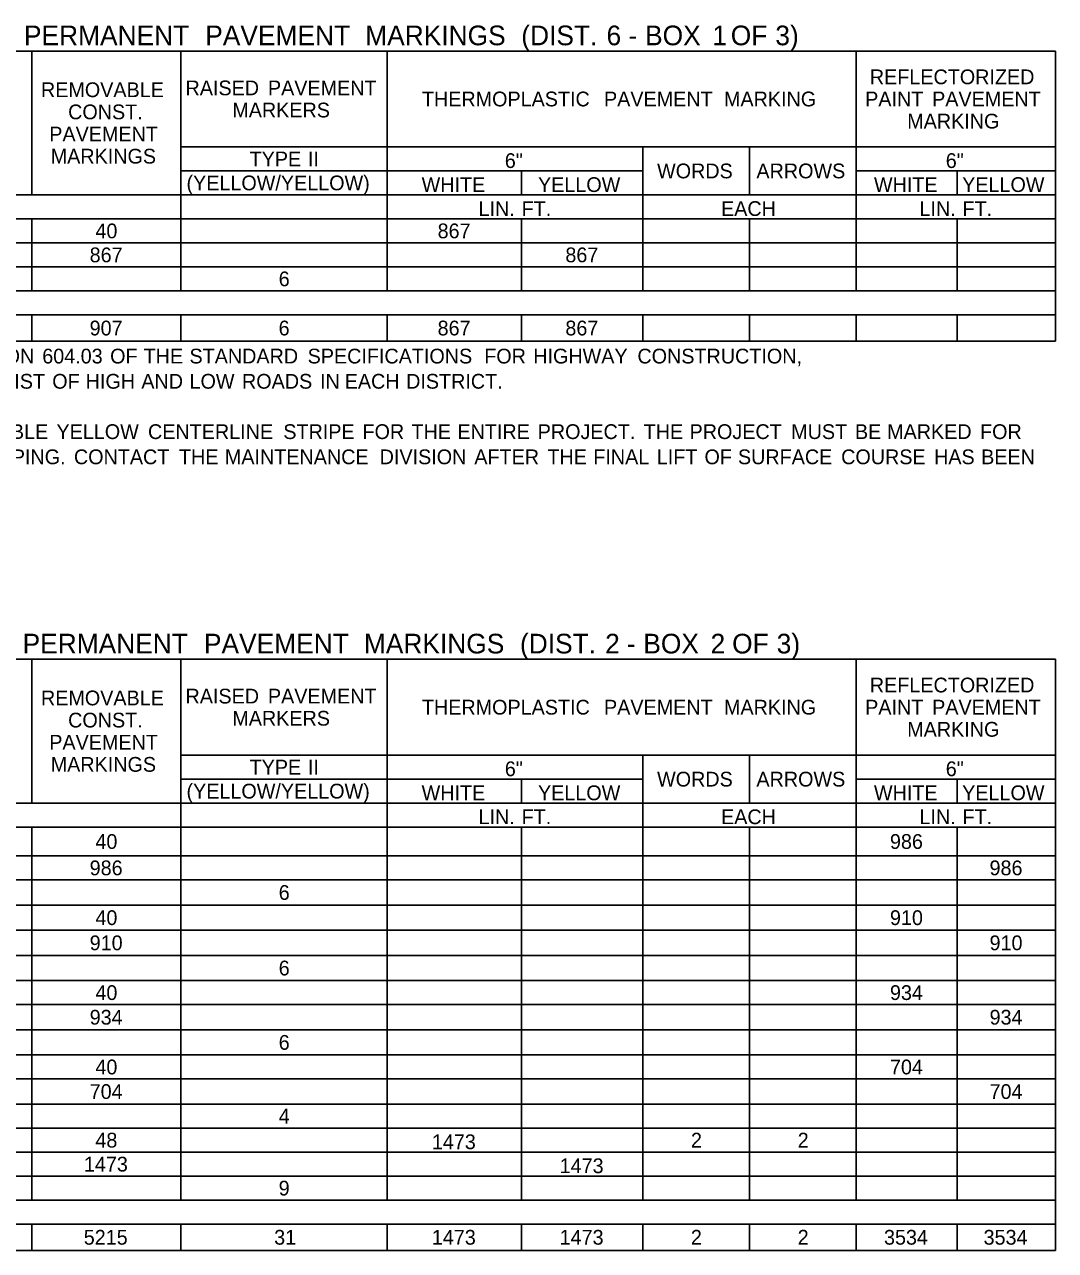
# Model space of a CAD drawing. Extents: x 542596 to 1930787, y -1948294 to 596640.
# Drawn here: x 558149.1 to 558568, y -1946597.7 to -1946099.4 of the extents above; entities that cross this region are included whole.
import ezdxf

# ---------------------------------------------------------------- set-up
doc = ezdxf.new("R2010")
doc.units = 0
doc.layers.add('Default', color=7, linetype='Continuous')

msp = doc.modelspace()

# ---------------------------------------------------------------- linework, layer by layer
at = {"layer": 'Default'}
for p, q in [((557797.21, -1946110.14), (558567.95, -1946110.14)), ((558152.11, -1946168.64), (558152.11, -1946110.14)), ((558212.56, -1946207.64), (558212.56, -1946110.14)), ((558296.41, -1946207.64), (558296.41, -1946110.14)), ((558487.03, -1946207.64), (558487.03, -1946110.14)), ((558567.95, -1946228.11), (558567.95, -1946110.14)), ((558212.56, -1946149.14), (558567.95, -1946149.14)), ((558400.25, -1946207.64), (558400.25, -1946149.14)), ((558400.25, -1946207.64), (558400.25, -1946149.14)), ((558443.64, -1946168.64), (558443.64, -1946149.14)), ((558212.56, -1946158.89), (558400.25, -1946158.89)), ((558351.01, -1946168.64), (558351.01, -1946158.89)), ((558487.03, -1946158.89), (558567.95, -1946158.89)), ((558527.98, -1946168.64), (558527.98, -1946158.89)), ((558031.21, -1946168.64), (558567.95, -1946168.64)), ((558212.56, -1946207.64), (558212.56, -1946168.64)), ((558400.25, -1946168.64), (558567.95, -1946168.64)), ((557797.21, -1946178.39), (558567.95, -1946178.39)), ((558152.11, -1946207.64), (558152.11, -1946178.39)), ((558152.11, -1946207.64), (558152.11, -1946178.39)), ((558296.41, -1946207.64), (558296.41, -1946178.39)), ((558351.01, -1946197.89), (558351.01, -1946178.39)), ((558351.01, -1946207.64), (558351.01, -1946178.39)), ((558443.64, -1946207.64), (558443.64, -1946178.39)), ((558443.64, -1946207.64), (558443.64, -1946178.39)), ((558487.03, -1946207.64), (558487.03, -1946178.39)), ((558527.98, -1946197.89), (558527.98, -1946178.39)), ((558527.98, -1946207.64), (558527.98, -1946178.39)), ((557971.25, -1946188.14), (558567.95, -1946188.14)), ((557971.25, -1946197.89), (558567.95, -1946197.89)), ((557797.21, -1946207.64), (558296.41, -1946207.64)), ((558091.66, -1946207.64), (558212.56, -1946207.64)), ((558212.56, -1946207.64), (558567.95, -1946207.64)), ((557797.21, -1946217.39), (558567.95, -1946217.39)), ((557797.21, -1946217.39), (558567.95, -1946217.39)), ((558152.11, -1946228.11), (558152.11, -1946217.39)), ((558152.11, -1946228.11), (558152.11, -1946217.39)), ((558212.56, -1946228.11), (558212.56, -1946217.39)), ((558212.56, -1946228.11), (558212.56, -1946217.39)), ((558296.41, -1946228.11), (558296.41, -1946217.39)), ((558296.41, -1946228.11), (558296.41, -1946217.39)), ((558351.01, -1946228.11), (558351.01, -1946217.39)), ((558351.01, -1946228.11), (558351.01, -1946217.39)), ((558400.25, -1946228.11), (558400.25, -1946217.39)), ((558400.25, -1946228.11), (558400.25, -1946217.39)), ((558443.64, -1946228.11), (558443.64, -1946217.39)), ((558443.64, -1946228.11), (558443.64, -1946217.39)), ((558487.03, -1946228.11), (558487.03, -1946217.39)), ((558487.03, -1946228.11), (558487.03, -1946217.39)), ((558527.98, -1946228.11), (558527.98, -1946217.39)), ((558527.98, -1946228.11), (558527.98, -1946217.39)), ((557797.21, -1946228.11), (558567.95, -1946228.11)), ((557797.21, -1946357.36), (558567.95, -1946357.36)), ((558152.11, -1946415.86), (558152.11, -1946357.36)), ((558212.56, -1946577.22), (558212.56, -1946357.36)), ((558296.41, -1946577.22), (558296.41, -1946357.36)), ((558487.03, -1946577.22), (558487.03, -1946357.36)), ((558567.95, -1946497.76), (558567.95, -1946357.36)), ((558212.56, -1946396.36), (558567.95, -1946396.36)), ((558400.25, -1946577.22), (558400.25, -1946396.36)), ((558400.25, -1946577.22), (558400.25, -1946396.36)), ((558443.64, -1946415.86), (558443.64, -1946396.36)), ((558212.56, -1946406.11), (558400.25, -1946406.11)), ((558351.01, -1946415.86), (558351.01, -1946406.11)), ((558487.03, -1946406.11), (558567.95, -1946406.11)), ((558527.98, -1946415.86), (558527.98, -1946406.11)), ((558031.21, -1946415.86), (558567.95, -1946415.86)), ((558212.56, -1946577.22), (558212.56, -1946415.86)), ((558400.25, -1946415.86), (558567.95, -1946415.86)), ((557797.21, -1946425.61), (558567.95, -1946425.61)), ((558152.11, -1946577.22), (558152.11, -1946425.61)), ((558152.11, -1946577.22), (558152.11, -1946425.61)), ((558212.56, -1946425.61), (558296.41, -1946425.61)), ((558296.41, -1946577.22), (558296.41, -1946425.61)), ((558351.01, -1946425.61), (558567.95, -1946425.61)), ((558351.01, -1946577.22), (558351.01, -1946425.61)), ((558351.01, -1946577.22), (558351.01, -1946425.61)), ((558443.64, -1946577.22), (558443.64, -1946425.61)), ((558443.64, -1946577.22), (558443.64, -1946425.61)), ((558487.03, -1946577.22), (558487.03, -1946425.61)), ((558527.98, -1946577.22), (558527.98, -1946425.61)), ((558527.98, -1946577.22), (558527.98, -1946425.61)), ((557971.25, -1946437.31), (558567.95, -1946437.31)), ((557971.25, -1946447.06), (558567.95, -1946447.06)), ((557797.21, -1946457.3), (558567.95, -1946457.3)), ((557971.25, -1946457.3), (558567.95, -1946457.3)), ((557971.25, -1946467.53), (558567.95, -1946467.53)), ((557971.25, -1946477.77), (558567.95, -1946477.77)), ((557797.21, -1946488.01), (558351.01, -1946488.01)), ((557971.25, -1946488.01), (558296.41, -1946488.01)), ((558296.41, -1946488.01), (558351.01, -1946488.01)), ((558351.01, -1946488.01), (558567.95, -1946488.01)), ((558351.01, -1946488.01), (558567.95, -1946488.01)), ((557971.25, -1946497.76), (558567.95, -1946497.76)), ((558567.95, -1946508), (558567.95, -1946497.76)), ((557971.25, -1946508), (558567.95, -1946508)), ((558351.01, -1946508), (558400.25, -1946508)), ((558400.25, -1946508), (558567.95, -1946508)), ((558567.95, -1946557.72), (558567.95, -1946508)), ((557797.21, -1946518.23), (558567.95, -1946518.23)), ((557971.25, -1946518.23), (558567.95, -1946518.23)), ((557971.25, -1946527.98), (558567.95, -1946527.98)), ((557971.25, -1946538.22), (558567.95, -1946538.22)), ((557797.21, -1946547.97), (558567.95, -1946547.97)), ((557971.25, -1946547.97), (558296.41, -1946547.97)), ((558351.01, -1946547.97), (558567.95, -1946547.97)), ((557971.25, -1946557.72), (558567.95, -1946557.72)), ((558567.95, -1946567.47), (558567.95, -1946557.72)), ((557971.25, -1946567.47), (558567.95, -1946567.47)), ((558351.01, -1946567.47), (558400.25, -1946567.47)), ((558400.25, -1946567.47), (558567.95, -1946567.47)), ((558567.95, -1946586.97), (558567.95, -1946567.47)), ((557797.21, -1946577.22), (558567.95, -1946577.22)), ((557797.21, -1946586.97), (558567.95, -1946586.97)), ((557797.21, -1946586.97), (558567.95, -1946586.97)), ((558152.11, -1946597.7), (558152.11, -1946586.97)), ((558152.11, -1946597.7), (558152.11, -1946586.97)), ((558212.56, -1946597.7), (558212.56, -1946586.97)), ((558212.56, -1946597.7), (558212.56, -1946586.97)), ((558296.41, -1946597.7), (558296.41, -1946586.97)), ((558296.41, -1946597.7), (558296.41, -1946586.97)), ((558351.01, -1946597.7), (558351.01, -1946586.97)), ((558351.01, -1946597.7), (558351.01, -1946586.97)), ((558400.25, -1946597.7), (558400.25, -1946586.97)), ((558400.25, -1946597.7), (558400.25, -1946586.97)), ((558443.64, -1946597.7), (558443.64, -1946586.97)), ((558443.64, -1946597.7), (558443.64, -1946586.97)), ((558487.03, -1946597.7), (558487.03, -1946586.97)), ((558487.03, -1946597.7), (558487.03, -1946586.97)), ((558527.98, -1946597.7), (558527.98, -1946586.97)), ((558527.98, -1946597.7), (558527.98, -1946586.97)), ((558567.95, -1946597.7), (558567.95, -1946586.97)), ((557797.21, -1946597.7), (558567.95, -1946597.7))]:
    msp.add_line(p, q, dxfattribs=at)

# ---------------------------------------------------------------- texts
for s, height, p in [(' PERMANENT', 8, (558145.87, -1946107.8)), (' PAVEMENT', 8, (558219.54, -1946107.8)), (' MARKINGS', 8, (558284.53, -1946107.8)), (' (DIST.', 8, (558347.94, -1946107.8)), (' 6', 8, (558382.57, -1946107.8)), (' BOX', 8, (558398.23, -1946107.8)), (' 1', 8, (558425.55, -1946107.8)), (' OF', 8, (558433.05, -1946107.8)), (' 3)', 8, (558451.16, -1946107.8)), (' -', 8, (558391.49, -1946107.8)), ('REFLECTORIZED', 6, (558492.53, -1946123.64)), ('REMOVABLE', 6, (558155.76, -1946128.89)), ('RAISED', 6, (558214.49, -1946128.14)), (' PAVEMENT', 6, (558245.75, -1946128.14)), ('THERMOPLASTIC', 6, (558310.53, -1946132.64)), (' PAVEMENT', 6, (558382.3, -1946132.64)), (' MARKING', 6, (558431.04, -1946132.64)), ('PAINT', 6, (558490.63, -1946132.64)), (' PAVEMENT', 6, (558515.61, -1946132.64)), ('CONST.', 6, (558166.79, -1946137.89)), ('MARKERS', 6, (558233.5, -1946137.14)), ('MARKING', 6, (558507.72, -1946141.64)), ('PAVEMENT', 6, (558159.13, -1946146.89)), ('MARKINGS', 6, (558159.72, -1946155.89)), ('TYPE', 6, (558240.53, -1946157.01)), (' II', 6, (558262.01, -1946157.01)), ('6"', 6, (558344.22, -1946157.69)), ('6"', 6, (558523.38, -1946157.69)), ('WORDS', 6, (558406.08, -1946161.89)), ('ARROWS', 6, (558446.44, -1946161.89)), ('(YELLOW/YELLOW)', 6, (558214.89, -1946166.76)), ('WHITE', 6, (558310.42, -1946167.44)), ('YELLOW', 6, (558357.71, -1946167.44)), ('WHITE', 6, (558494.2, -1946167.44)), ('YELLOW', 6, (558530.04, -1946167.44)), ('LIN.', 6, (558333.54, -1946177.19)), (' FT.', 6, (558348.8, -1946177.19)), ('EACH', 6, (558432.08, -1946177.19)), ('LIN.', 6, (558512.7, -1946177.19)), (' FT.', 6, (558527.95, -1946177.19)), ('40', 6, (558177.88, -1946186.26)), ('867', 6, (558316.91, -1946186.26)), ('867', 6, (558175.54, -1946196.01)), ('867', 6, (558368.83, -1946196.01)), ('6', 6, (558252.35, -1946205.76)), ('907', 6, (558175.53, -1946225.75)), ('6', 6, (558252.31, -1946225.75)), ('867', 6, (558316.91, -1946225.75)), ('867', 6, (558368.83, -1946225.75)), (' SECTION', 6, (558115.15, -1946237.15)), (' 604.03', 6, (558154.05, -1946237.15)), (' OF', 6, (558181.63, -1946237.15)), (' THE', 6, (558195.22, -1946237.15)), (' STANDARD', 6, (558213.87, -1946237.15)), (' SPECIFICATIONS', 6, (558261.87, -1946237.15)), (' FOR', 6, (558333.63, -1946237.15)), (' HIGHWAY', 6, (558353.55, -1946237.15)), (' CONSTRUCTION,', 6, (558395.87, -1946237.15)), (' LIST', 6, (558138.24, -1946247.39)), (' OF', 6, (558158.11, -1946247.39)), (' HIGH', 6, (558171.69, -1946247.39)), (' AND', 6, (558194.3, -1946247.39)), (' LOW', 6, (558213.89, -1946247.39)), (' ROADS', 6, (558235.21, -1946247.39)), (' IN', 6, (558266.92, -1946247.39)), (' EACH', 6, (558276.94, -1946247.39)), (' DISTRICT.', 6, (558301.89, -1946247.39)), (' DOUBLE', 6, (558123.49, -1946267.86)), (' YELLOW', 6, (558159.84, -1946267.86)), (' CENTERLINE', 6, (558197.01, -1946267.86)), (' STRIPE', 6, (558252, -1946267.86)), (' FOR', 6, (558284.17, -1946267.86)), (' THE', 6, (558304.08, -1946267.86)), (' ENTIRE', 6, (558322.73, -1946267.86)), (' PROJECT.', 6, (558355.35, -1946267.86)), (' THE', 6, (558398.41, -1946267.86)), (' PROJECT', 6, (558417.06, -1946267.86)), (' MUST', 6, (558458.35, -1946267.86)), (' BE', 6, (558484.26, -1946267.86)), (' MARKED', 6, (558497.33, -1946267.86)), (' FOR', 6, (558535.08, -1946267.86)), (' STRIPING.', 6, (558123.4, -1946278.1)), (' CONTACT', 6, (558166.92, -1946278.1)), (' THE', 6, (558209.6, -1946278.1)), (' MAINTENANCE', 6, (558228.25, -1946278.1)), (' DIVISION', 6, (558291.15, -1946278.1)), (' AFTER', 6, (558329.6, -1946278.1)), (' THE', 6, (558359.29, -1946278.1)), (' FINAL', 6, (558377.94, -1946278.1)), (' LIFT', 6, (558403.73, -1946278.1)), (' OF', 6, (558423.12, -1946278.1)), (' SURFACE', 6, (558436.71, -1946278.1)), (' COURSE', 6, (558478.65, -1946278.1)), (' HAS', 6, (558516.4, -1946278.1)), (' BEEN', 6, (558535.53, -1946278.1)), (' PERMANENT', 8, (558145.32, -1946355.02)), (' PAVEMENT', 8, (558219, -1946355.02)), (' MARKINGS', 8, (558283.99, -1946355.02)), (' (DIST.', 8, (558347.4, -1946355.02)), (' 2', 8, (558382.02, -1946355.02)), (' BOX', 8, (558397.52, -1946355.02)), (' 2', 8, (558424.84, -1946355.02)), (' OF', 8, (558433.6, -1946355.02)), (' 3)', 8, (558451.71, -1946355.02)), (' -', 8, (558390.78, -1946355.02)), ('REFLECTORIZED', 6, (558492.53, -1946370.86)), ('REMOVABLE', 6, (558155.76, -1946376.11)), ('RAISED', 6, (558214.49, -1946375.36)), (' PAVEMENT', 6, (558245.75, -1946375.36)), ('MARKERS', 6, (558233.5, -1946384.36)), ('THERMOPLASTIC', 6, (558310.53, -1946379.86)), (' PAVEMENT', 6, (558382.3, -1946379.86)), (' MARKING', 6, (558431.04, -1946379.86)), ('PAINT', 6, (558490.63, -1946379.86)), (' PAVEMENT', 6, (558515.61, -1946379.86)), ('CONST.', 6, (558166.79, -1946385.11)), ('MARKING', 6, (558507.72, -1946388.86)), ('PAVEMENT', 6, (558159.13, -1946394.11)), ('MARKINGS', 6, (558159.72, -1946403.11)), ('TYPE', 6, (558240.53, -1946404.23)), (' II', 6, (558262.01, -1946404.23)), ('6"', 6, (558344.22, -1946404.91)), ('WORDS', 6, (558406.08, -1946409.11)), ('ARROWS', 6, (558446.44, -1946409.11)), ('6"', 6, (558523.38, -1946404.91)), ('(YELLOW/YELLOW)', 6, (558214.89, -1946413.98)), ('WHITE', 6, (558310.42, -1946414.66)), ('YELLOW', 6, (558357.71, -1946414.66)), ('WHITE', 6, (558494.2, -1946414.66)), ('YELLOW', 6, (558530.04, -1946414.66)), ('LIN.', 6, (558333.54, -1946424.41)), (' FT.', 6, (558348.8, -1946424.41)), ('EACH', 6, (558432.08, -1946424.41)), ('LIN.', 6, (558512.7, -1946424.41)), (' FT.', 6, (558527.95, -1946424.41)), ('40', 6, (558177.88, -1946434.46)), ('986', 6, (558500.7, -1946434.46)), ('986', 6, (558175.54, -1946445.18)), ('986', 6, (558541.16, -1946445.18)), ('6', 6, (558252.35, -1946455.18)), ('40', 6, (558177.88, -1946465.42)), ('910', 6, (558500.71, -1946465.42)), ('910', 6, (558175.55, -1946475.65)), ('910', 6, (558541.17, -1946475.65)), ('6', 6, (558252.35, -1946485.89)), ('40', 6, (558177.88, -1946495.88)), ('934', 6, (558500.71, -1946495.88)), ('934', 6, (558175.55, -1946505.88)), ('934', 6, (558541.18, -1946505.88)), ('6', 6, (558252.35, -1946516.12)), ('40', 6, (558177.88, -1946526.11)), ('704', 6, (558500.71, -1946526.11)), ('704', 6, (558175.55, -1946536.1)), ('704', 6, (558541.18, -1946536.1)), ('4', 6, (558252.36, -1946546.1)), ('48', 6, (558177.86, -1946555.85)), ('1473', 6, (558314.58, -1946556.52)), ('2', 6, (558419.84, -1946555.85)), ('2', 6, (558463.22, -1946555.85)), ('1473', 6, (558173.21, -1946565.6)), ('1473', 6, (558366.5, -1946566.27)), ('9', 6, (558252.34, -1946575.35)), ('5215', 6, (558173.14, -1946595.33)), ('31', 6, (558250.51, -1946595.33)), ('1473', 6, (558314.57, -1946595.33)), ('1473', 6, (558366.49, -1946595.33)), ('2', 6, (558419.82, -1946595.33)), ('2', 6, (558463.21, -1946595.33)), ('3534', 6, (558498.28, -1946595.33)), ('3534', 6, (558538.74, -1946595.33))]:
    msp.add_text(s, height=height, dxfattribs=at).set_placement(p)

doc.saveas('drawing.dxf')
